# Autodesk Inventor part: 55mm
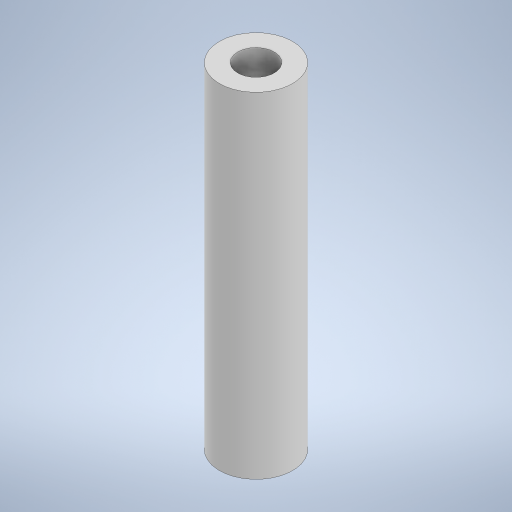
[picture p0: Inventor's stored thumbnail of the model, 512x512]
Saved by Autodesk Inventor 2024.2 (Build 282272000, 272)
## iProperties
Created: 2024-05
Part Number: 55mm
Material: Generic
Document SubType Name: Modeling
Designer: Karsten
Density: 1 g/cm^3
Appearance: Default
Author: Karsten
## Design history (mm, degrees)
sketch "Sketch1"
  geometry: C1 r 3 at (0, 0); C2 r 6 at (0, 0); 1 further point
  constraints: 2 centre point, 2 coincident
  dimensions: "d0" = 6 diameter of C1; "d1" = 12 diameter of C2
extrude "Extrusion1" new body sketch "Sketch1" distance "d2" = 55; taper "d3" = 0 deg
body "Solid1"
